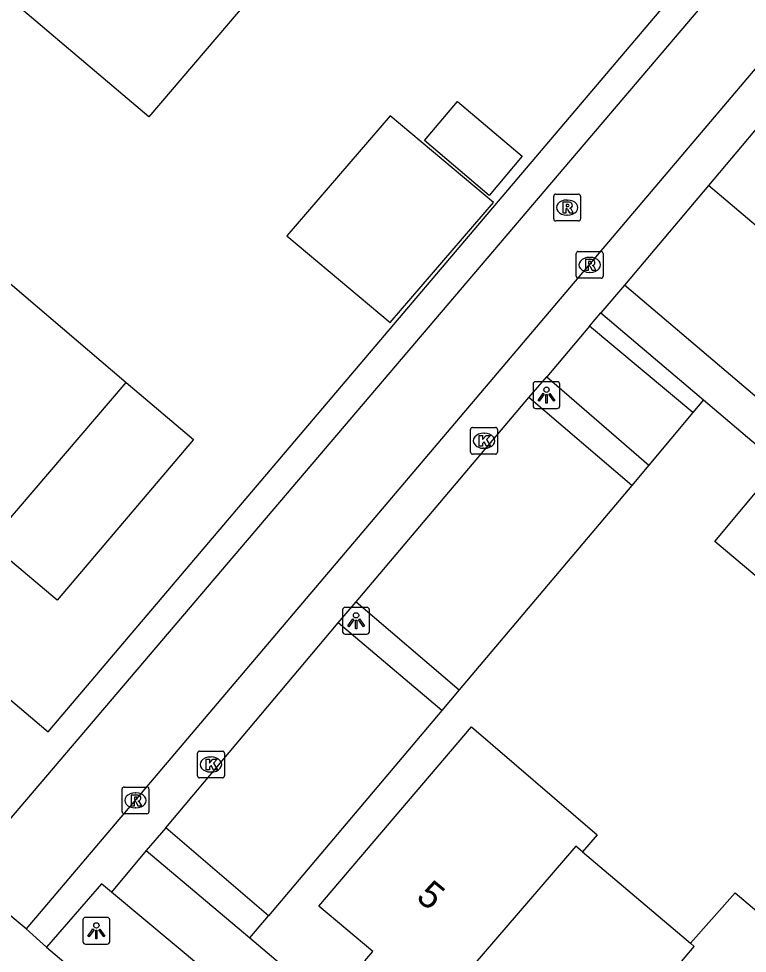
# Model space of a CAD drawing. Extents: x 156414 to 157775, y 382335 to 383765.
# Drawn here: x 156860.52 to 156887.69, y 382493.58 to 382528.45 of the extents above; entities that cross this region are included whole.
import ezdxf

# ---------------------------------------------------------------- set-up
doc = ezdxf.new("R2010")
doc.units = 0
for name, color, linetype in [('IMGEO_Haag', 7, 'Continuous'), ('IMGEO_Kolk', 7, 'Continuous'), ('IMGEO_Lichtpunt', 7, 'Continuous'), ('IMGEO_Pand', 7, 'Continuous'), ('IMGEO_Pand_nummerreeks', 7, 'Continuous'), ('IMGEO_Parkeervlak_open', 7, 'Continuous'), ('IMGEO_Rijbaan_lokaal_halfverhard', 7, 'Continuous'), ('IMGEO_Rijbaan_lokaal_open', 7, 'Continuous'), ('IMGEO_Rioolput', 7, 'Continuous'), ('IMGEO_Voetpad_open', 7, 'Continuous')]:
    doc.layers.add(name, color=color, linetype=linetype)

msp = doc.modelspace()

# ---------------------------------------------------------------- linework, layer by layer
at = {"layer": 'IMGEO_Haag'}
for points in [[(156886.06, 382514.223), (156885.664, 382513.751)], [(156884.022, 382511.795), (156883.386, 382511.032)], [(156876.951, 382503.406), (156876.303, 382502.638)], [(156869.142, 382494.152), (156869.838, 382494.977)]]:
    msp.add_lwpolyline(points, dxfattribs=at)
at = {"layer": 'IMGEO_Kolk'}
for p, q in [((156877.451, 382513.2), (156878.303, 382513.2)), ((156877.376, 382512.274), (156877.376, 382513.126)), ((156877.864, 382512.98), (156877.889, 382512.98)), ((156878.377, 382513.126), (156878.377, 382512.274)), ((156878.303, 382512.2), (156877.451, 382512.2)), ((156877.887, 382512.42), (156877.862, 382512.42)), ((156867.191, 382500.197), (156867.191, 382501.049)), ((156867.266, 382501.123), (156868.118, 382501.123)), ((156868.192, 382501.049), (156868.192, 382500.197)), ((156867.679, 382500.903), (156867.704, 382500.903)), ((156867.702, 382500.343), (156867.677, 382500.343)), ((156868.118, 382500.123), (156867.266, 382500.123))]:
    msp.add_line(p, q, dxfattribs=at)
for points in [[(156877.451, 382513.2), (156878.303, 382513.2)], [(156877.376, 382512.274), (156877.376, 382513.126)], [(156877.697, 382512.9), (156877.82, 382512.9), (156877.82, 382512.749), (156877.95, 382512.9), (156878.114, 382512.9), (156877.968, 382512.749), (156878.121, 382512.5), (156877.969, 382512.5), (156877.884, 382512.664), (156877.82, 382512.597), (156877.82, 382512.5), (156877.697, 382512.5), (156877.697, 382512.9)], [(156878.377, 382513.126), (156878.377, 382512.274)], [(156878.303, 382512.2), (156877.451, 382512.2)], [(156867.191, 382500.197), (156867.191, 382501.049)], [(156867.266, 382501.123), (156868.118, 382501.123)], [(156868.192, 382501.049), (156868.192, 382500.197)], [(156867.512, 382500.823), (156867.635, 382500.823), (156867.635, 382500.672), (156867.765, 382500.823), (156867.929, 382500.823), (156867.783, 382500.672), (156867.936, 382500.423), (156867.784, 382500.423), (156867.699, 382500.587), (156867.635, 382500.52), (156867.635, 382500.423), (156867.512, 382500.423), (156867.512, 382500.823)], [(156868.118, 382500.123), (156867.266, 382500.123)]]:
    msp.add_lwpolyline(points, dxfattribs=at)
for centre, start, end in [((156877.453, 382513.124), 91.552, 178.448), ((156877.453, 382513.124), 91.552, 178.448), ((156878.301, 382513.124), 1.552, 88.448), ((156878.301, 382513.124), 1.552, 88.448), ((156877.453, 382512.276), 181.552, 268.448), ((156877.453, 382512.276), 181.552, 268.448), ((156878.301, 382512.276), 271.552, 358.448), ((156878.301, 382512.276), 271.552, 358.448), ((156867.268, 382501.047), 91.552, 178.448), ((156867.268, 382501.047), 91.552, 178.448), ((156868.116, 382501.047), 1.552, 88.448), ((156868.116, 382501.047), 1.552, 88.448), ((156867.268, 382500.199), 181.552, 268.448), ((156867.268, 382500.199), 181.552, 268.448), ((156868.116, 382500.199), 271.552, 358.448), ((156868.116, 382500.199), 271.552, 358.448)]:
    msp.add_arc(centre, 0.0765, start, end, dxfattribs=at)
for centre, major_axis, ratio, start_param, end_param in [((156877.863, 382512.7), (-0.387, 0.002), 0.722429, 4.712389, 7.853982), ((156877.888, 382512.7), (-0.39, 0.002), 0.717154, 1.570796, 4.712389), ((156867.678, 382500.623), (-0.387, 0.002), 0.722429, 4.712389, 7.853982), ((156867.703, 382500.623), (-0.39, 0.002), 0.717154, 1.570796, 4.712389)]:
    msp.add_ellipse(centre, major_axis=major_axis, ratio=ratio, start_param=start_param, end_param=end_param, dxfattribs=at)
at = {"layer": 'IMGEO_Lichtpunt'}
for p, q in [((156880.607, 382514.902), (156879.799, 382514.902)), ((156880.607, 382514.902), (156879.799, 382514.902)), ((156879.705, 382514.807), (156879.705, 382514)), ((156879.705, 382514.807), (156879.705, 382514)), ((156880.701, 382514), (156880.701, 382514.807)), ((156880.701, 382514), (156880.701, 382514.807)), ((156879.799, 382513.906), (156880.607, 382513.906)), ((156879.799, 382513.906), (156880.607, 382513.906)), ((156872.604, 382506.39), (156872.604, 382505.583)), ((156872.604, 382506.39), (156872.604, 382505.583)), ((156873.506, 382506.485), (156872.698, 382506.485)), ((156873.506, 382506.485), (156872.698, 382506.485)), ((156873.6, 382505.583), (156873.6, 382506.39)), ((156873.6, 382505.583), (156873.6, 382506.39)), ((156872.698, 382505.489), (156873.506, 382505.489)), ((156872.698, 382505.489), (156873.506, 382505.489)), ((156862.92, 382494.822), (156862.92, 382494.015)), ((156862.92, 382494.822), (156862.92, 382494.015)), ((156863.822, 382494.917), (156863.014, 382494.917)), ((156863.822, 382494.917), (156863.014, 382494.917)), ((156863.916, 382494.015), (156863.916, 382494.822)), ((156863.916, 382494.015), (156863.916, 382494.822)), ((156863.014, 382493.921), (156863.822, 382493.921)), ((156863.014, 382493.921), (156863.822, 382493.921))]:
    msp.add_line(p, q, dxfattribs=at)
for points in [[(156880.079, 382514.471), (156880.118, 382514.443), (156879.93, 382514.181), (156879.892, 382514.208), (156880.079, 382514.471)], [(156880.181, 382514.423), (156880.228, 382514.423), (156880.228, 382514.101), (156880.181, 382514.101), (156880.181, 382514.423)], [(156880.291, 382514.443), (156880.329, 382514.47), (156880.516, 382514.208), (156880.477, 382514.18), (156880.291, 382514.443)], [(156872.978, 382506.054), (156873.017, 382506.026), (156872.829, 382505.764), (156872.791, 382505.791), (156872.978, 382506.054)], [(156873.08, 382506.006), (156873.127, 382506.006), (156873.127, 382505.684), (156873.08, 382505.684), (156873.08, 382506.006)], [(156873.19, 382506.026), (156873.228, 382506.053), (156873.415, 382505.791), (156873.376, 382505.763), (156873.19, 382506.026)], [(156863.294, 382494.486), (156863.333, 382494.458), (156863.145, 382494.196), (156863.107, 382494.223), (156863.294, 382494.486)], [(156863.396, 382494.438), (156863.443, 382494.438), (156863.443, 382494.116), (156863.396, 382494.116), (156863.396, 382494.438)], [(156863.506, 382494.458), (156863.544, 382494.485), (156863.731, 382494.223), (156863.692, 382494.195), (156863.506, 382494.458)]]:
    msp.add_lwpolyline(points, dxfattribs=at)
for centre in [(156880.204, 382514.605), (156873.103, 382506.188), (156863.419, 382494.62)]:
    msp.add_circle(centre, 0.0994, dxfattribs=at)
for centre, start, end in [((156879.799, 382514.807), 90, 180), ((156879.799, 382514.807), 90, 180), ((156880.607, 382514.807), 0, 90), ((156880.607, 382514.807), 0, 90), ((156879.799, 382514), 180, 270), ((156879.799, 382514), 180, 270), ((156880.607, 382514), 270, 0), ((156880.607, 382514), 270, 360), ((156872.698, 382506.39), 90, 180), ((156872.698, 382506.39), 90, 180), ((156873.506, 382506.39), 0, 90), ((156873.506, 382506.39), 0, 90), ((156872.698, 382505.583), 180, 270), ((156872.698, 382505.583), 180, 270), ((156873.506, 382505.583), 270, 0), ((156873.506, 382505.583), 270, 360), ((156863.014, 382494.822), 90, 180), ((156863.014, 382494.822), 90, 180), ((156863.822, 382494.822), 0, 90), ((156863.822, 382494.822), 0, 90), ((156863.014, 382494.015), 180, 270), ((156863.014, 382494.015), 180, 270), ((156863.822, 382494.015), 270, 0), ((156863.822, 382494.015), 270, 360)]:
    msp.add_arc(centre, 0.0946, start, end, dxfattribs=at)
at = {"layer": 'IMGEO_Pand'}
for points in [[(156869.14, 382529.214), (156865.381, 382524.784), (156857.671, 382531.315), (156861.441, 382535.754)], [(156875.652, 382523.901), (156876.889, 382525.359), (156879.3, 382523.314), (156878.063, 382521.856), (156875.652, 382523.901)], [(156878.228, 382521.59), (156874.379, 382524.823), (156870.528, 382520.343), (156874.377, 382517.11), (156878.228, 382521.59)], [(156859.768, 382518.924), (156864.531, 382514.88)], [(156864.531, 382514.88), (156867.043, 382512.747), (156861.953, 382506.75), (156859.41, 382508.896)], [(156859.41, 382508.896), (156864.531, 382514.88)], [(156889.227, 382506.747), (156889.173, 382506.683), (156886.477, 382508.947), (156888.686, 382511.579), (156891.383, 382509.315)], [(156876.155, 382491.595), (156875.863, 382491.256), (156873.432, 382493.297), (156873.726, 382493.645), (156871.721, 382495.337), (156877.405, 382502.024), (156882.1, 382497.998), (156881.543, 382497.369)], [(156881.543, 382497.369), (156881.301, 382497.575), (156876.155, 382491.595)], [(156881.543, 382497.369), (156885.573, 382493.956)], [(156885.573, 382493.956), (156887.239, 382495.838), (156891.913, 382491.884), (156891.713, 382491.658)], [(156880.337, 382487.466), (156885.718, 382493.833), (156885.573, 382493.956)]]:
    msp.add_lwpolyline(points, dxfattribs=at)
at = {"layer": 'IMGEO_Parkeervlak_open'}
for points in [[(156885.664, 382513.751), (156881.815, 382516.982)], [(156880.214, 382515.091), (156884.022, 382511.795)], [(156883.386, 382511.032), (156879.541, 382514.314)], [(156885.664, 382513.751), (156884.022, 382511.795)], [(156883.386, 382511.032), (156876.951, 382503.406)], [(156873.102, 382506.693), (156876.951, 382503.406)], [(156876.303, 382502.638), (156872.437, 382505.909)], [(156876.303, 382502.638), (156869.838, 382494.977)], [(156869.838, 382494.977), (156866.004, 382498.26)]]:
    msp.add_lwpolyline(points, dxfattribs=at)
at = {"layer": 'IMGEO_Rijbaan_lokaal_halfverhard'}
for points in [[(156886.25, 382522.23), (156883.11, 382518.509)], [(156890.052, 382519.003), (156886.25, 382522.23)], [(156904.371, 382500.449), (156883.11, 382518.509)]]:
    msp.add_lwpolyline(points, dxfattribs=at)
at = {"layer": 'IMGEO_Rijbaan_lokaal_open'}
for points in [[(156858.4, 382496.484), (156890.546, 382534.28)], [(156888.054, 382526.647), (156860.796, 382494.49)], [(156860.796, 382494.49), (156858.4, 382496.484)]]:
    msp.add_lwpolyline(points, dxfattribs=at)
at = {"layer": 'IMGEO_Rioolput'}
for p, q in [((156880.549, 382521.901), (156881.401, 382521.901)), ((156880.474, 382520.975), (156880.474, 382521.827)), ((156880.962, 382521.681), (156880.987, 382521.681)), ((156881.475, 382521.827), (156881.475, 382520.975)), ((156881.401, 382520.901), (156880.549, 382520.901)), ((156880.985, 382521.121), (156880.96, 382521.121)), ((156881.317, 382518.838), (156881.317, 382519.69)), ((156881.392, 382519.764), (156882.244, 382519.764)), ((156881.805, 382519.544), (156881.83, 382519.544)), ((156882.318, 382519.69), (156882.318, 382518.838)), ((156882.244, 382518.764), (156881.392, 382518.764)), ((156881.828, 382518.984), (156881.803, 382518.984)), ((156864.38, 382498.857), (156864.38, 382499.709)), ((156864.455, 382499.783), (156865.307, 382499.783)), ((156864.868, 382499.563), (156864.893, 382499.563)), ((156865.381, 382499.709), (156865.381, 382498.857)), ((156864.891, 382499.003), (156864.866, 382499.003)), ((156865.307, 382498.783), (156864.455, 382498.783))]:
    msp.add_line(p, q, dxfattribs=at)
for points in [[(156880.549, 382521.901), (156881.401, 382521.901)], [(156880.474, 382520.975), (156880.474, 382521.827)], [(156881.063, 382521.599), (156880.811, 382521.601), (156880.811, 382521.201)], [(156880.989, 382521.52), (156880.935, 382521.52), (156880.935, 382521.439)], [(156881.475, 382521.827), (156881.475, 382520.975)], [(156880.811, 382521.201), (156880.935, 382521.201), (156880.935, 382521.363), (156880.946, 382521.363)], [(156880.935, 382521.439), (156880.987, 382521.439)], [(156880.993, 382521.334), (156881.064, 382521.201), (156881.204, 382521.201), (156881.139, 382521.327)], [(156881.401, 382520.901), (156880.549, 382520.901)], [(156881.317, 382518.838), (156881.317, 382519.69)], [(156881.392, 382519.764), (156882.244, 382519.764)], [(156881.906, 382519.462), (156881.654, 382519.464), (156881.654, 382519.064)], [(156882.318, 382519.69), (156882.318, 382518.838)], [(156881.654, 382519.064), (156881.778, 382519.064), (156881.778, 382519.226), (156881.789, 382519.226)], [(156881.832, 382519.383), (156881.778, 382519.383), (156881.778, 382519.302)], [(156881.778, 382519.302), (156881.83, 382519.302)], [(156881.836, 382519.197), (156881.907, 382519.064), (156882.047, 382519.064), (156881.982, 382519.19)], [(156882.244, 382518.764), (156881.392, 382518.764)], [(156864.38, 382498.857), (156864.38, 382499.709)], [(156864.455, 382499.783), (156865.307, 382499.783)], [(156865.381, 382499.709), (156865.381, 382498.857)], [(156864.969, 382499.481), (156864.717, 382499.483), (156864.717, 382499.083)], [(156864.717, 382499.083), (156864.841, 382499.083), (156864.841, 382499.245), (156864.852, 382499.245)], [(156864.895, 382499.402), (156864.841, 382499.402), (156864.841, 382499.321)], [(156864.841, 382499.321), (156864.893, 382499.321)], [(156864.899, 382499.216), (156864.97, 382499.083), (156865.11, 382499.083), (156865.045, 382499.209)], [(156865.307, 382498.783), (156864.455, 382498.783)]]:
    msp.add_lwpolyline(points, dxfattribs=at)
for centre, radius, start, end in [((156880.551, 382521.825), 0.0765, 91.552, 178.448), ((156880.551, 382521.825), 0.0765, 91.552, 178.448), ((156881.399, 382521.825), 0.0765, 1.552, 88.448), ((156881.399, 382521.825), 0.0765, 1.552, 88.448), ((156880.995, 382521.424), 0.0964, 77.0061, 93.1865), ((156881.009, 382521.481), 0.0378, 276.6634, 79.6772), ((156881.062, 382521.489), 0.109, 350.3612, 89.416), ((156880.945, 382521.31), 0.0533, 26.0293, 88.6989), ((156880.971, 382521.628), 0.19, 274.7715, 282.9687), ((156881.06, 382521.489), 0.112, 277.5842, 350.9817), ((156881.044, 382521.274), 0.108, 29.5134, 73.7905), ((156880.551, 382520.977), 0.0765, 181.552, 268.448), ((156880.551, 382520.977), 0.0765, 181.552, 268.448), ((156881.399, 382520.977), 0.0765, 271.552, 358.448), ((156881.399, 382520.977), 0.0765, 271.552, 358.448), ((156881.394, 382519.688), 0.0765, 91.552, 178.448), ((156881.394, 382519.688), 0.0765, 91.552, 178.448), ((156881.905, 382519.352), 0.109, 350.3612, 89.416), ((156882.242, 382519.688), 0.0765, 1.552, 88.448), ((156882.242, 382519.688), 0.0765, 1.552, 88.448), ((156881.788, 382519.173), 0.0533, 26.0293, 88.6989), ((156881.814, 382519.491), 0.19, 274.7715, 282.9687), ((156881.838, 382519.287), 0.0964, 77.0061, 93.1865), ((156881.852, 382519.344), 0.0378, 276.6634, 79.6772), ((156881.903, 382519.352), 0.112, 277.5842, 350.9817), ((156881.887, 382519.137), 0.108, 29.5134, 73.7905), ((156881.394, 382518.84), 0.0765, 181.552, 268.448), ((156881.394, 382518.84), 0.0765, 181.552, 268.448), ((156882.242, 382518.84), 0.0765, 271.552, 358.448), ((156882.242, 382518.84), 0.0765, 271.552, 358.448), ((156864.457, 382499.707), 0.0765, 91.552, 178.448), ((156864.457, 382499.707), 0.0765, 91.552, 178.448), ((156865.305, 382499.707), 0.0765, 1.552, 88.448), ((156865.305, 382499.707), 0.0765, 1.552, 88.448), ((156864.851, 382499.192), 0.0533, 26.0293, 88.6989), ((156864.877, 382499.51), 0.19, 274.7715, 282.9687), ((156864.901, 382499.306), 0.0964, 77.0061, 93.1865), ((156864.915, 382499.363), 0.0378, 276.6634, 79.6772), ((156864.968, 382499.371), 0.109, 350.3612, 89.416), ((156864.966, 382499.371), 0.112, 277.5842, 350.9817), ((156864.95, 382499.156), 0.108, 29.5134, 73.7905), ((156864.457, 382498.859), 0.0765, 181.552, 268.448), ((156864.457, 382498.859), 0.0765, 181.552, 268.448), ((156865.305, 382498.859), 0.0765, 271.552, 358.448), ((156865.305, 382498.859), 0.0765, 271.552, 358.448)]:
    msp.add_arc(centre, radius, start, end, dxfattribs=at)
for centre, major_axis, ratio, start_param, end_param in [((156880.961, 382521.401), (-0.387, 0.002), 0.722429, 4.712389, 7.853982), ((156880.986, 382521.401), (-0.39, 0.002), 0.717154, 1.570796, 4.712389), ((156881.804, 382519.264), (-0.387, 0.002), 0.722429, 4.712389, 7.853982), ((156881.829, 382519.264), (-0.39, 0.002), 0.717154, 1.570796, 4.712389), ((156864.867, 382499.283), (-0.387, 0.002), 0.722429, 4.712389, 7.853982), ((156864.892, 382499.283), (-0.39, 0.002), 0.717154, 1.570796, 4.712389)]:
    msp.add_ellipse(centre, major_axis=major_axis, ratio=ratio, start_param=start_param, end_param=end_param, dxfattribs=at)
at = {"layer": 'IMGEO_Voetpad_open'}
for points in [[(156843.15, 382517.517), (156844.136, 382516.672), (156861.628, 382501.843), (156889.706, 382534.959)], [(156889.219, 382525.754), (156886.25, 382522.23)], [(156883.11, 382518.509), (156882.233, 382517.47)], [(156881.815, 382516.982), (156882.233, 382517.47)], [(156882.233, 382517.47), (156886.06, 382514.223)], [(156881.815, 382516.982), (156880.214, 382515.091)], [(156879.541, 382514.314), (156880.214, 382515.091)], [(156873.102, 382506.693), (156879.541, 382514.314)], [(156886.06, 382514.223), (156923.115, 382482.783)], [(156872.437, 382505.909), (156873.102, 382506.693)], [(156866.004, 382498.26), (156872.437, 382505.909)], [(156866.004, 382498.26), (156865.283, 382497.419)], [(156865.283, 382497.419), (156863.984, 382495.86)], [(156865.283, 382497.419), (156869.142, 382494.152)], [(156863.984, 382495.86), (156863.611, 382496.172), (156861.565, 382493.813)], [(156893.399, 382470.983), (156870.843, 382490.126), (156863.984, 382495.86)], [(156861.565, 382493.813), (156860.796, 382494.49)], [(156869.142, 382494.152), (156906.194, 382462.781)], [(156861.565, 382493.813), (156865.838, 382490.195)]]:
    msp.add_lwpolyline(points, dxfattribs=at)

# ---------------------------------------------------------------- texts
at = {"layer": 'IMGEO_Pand_nummerreeks'}
msp.add_text('5', height=1, rotation=320.4602, dxfattribs=at).set_placement((156875.301, 382495.608))

doc.saveas('drawing.dxf')
